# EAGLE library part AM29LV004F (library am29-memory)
4-Megabit FLASH MEMORY (512 K x 8 bit/256 K x 16 bit) 3 V-only
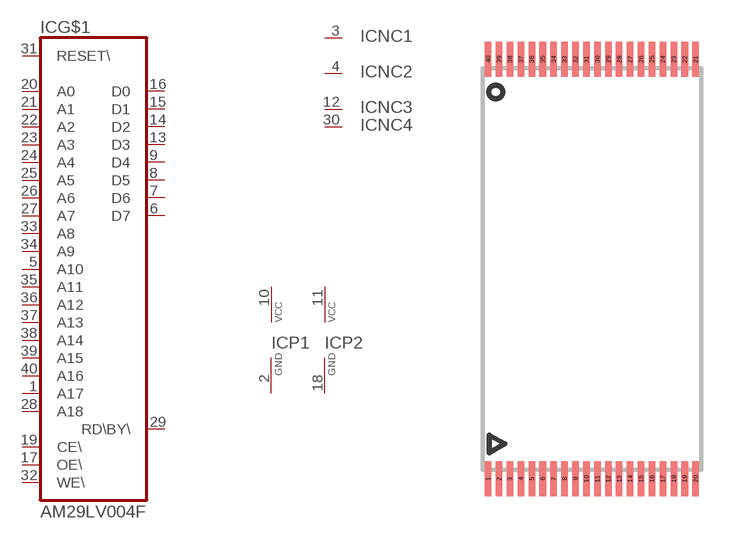
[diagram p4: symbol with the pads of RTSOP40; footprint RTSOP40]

Designator prefix IC; gates G$1=29LV004 NC1=NC NC2=NC NC3=NC NC4=NC P1=VCC-GND P2=VCC-GND

## AM29LV004F  [RTSOP40]
1  G$1:A17  in
2  P1:GND  pwr
3  NC1:NC  nc
4  NC2:NC  nc
5  G$1:A10  in
6  G$1:D7  hiz
7  G$1:D6  hiz
8  G$1:D5  hiz
9  G$1:D4  hiz
10  P1:VCC  pwr
11  P2:VCC  pwr
12  NC3:NC  nc
13  G$1:D3  hiz
14  G$1:D2  hiz
15  G$1:D1  hiz
16  G$1:D0  hiz
17  G$1:OE\  in
18  P2:GND  pwr
19  G$1:CE\  in
20  G$1:A0  in
21  G$1:A1  in
22  G$1:A2  in
23  G$1:A3  in
24  G$1:A4  in
25  G$1:A5  in
26  G$1:A6  in
27  G$1:A7  in
28  G$1:A18  in
29  G$1:RD\BY\  out
30  NC4:NC  nc
31  G$1:RESET\  in
32  G$1:WE\  in
33  G$1:A8  in
34  G$1:A9  in
35  G$1:A11  in
36  G$1:A12  in
37  G$1:A13  in
38  G$1:A14  in
39  G$1:A15  in
40  G$1:A16  in

## Footprint RTSOP40 (pad centres in mm)
Reverse TSOP40
smd 0.3 x 1.6: 1 -4.75,-9.6; 2 -4.25,-9.6; 3 -3.75,-9.6; 4 -3.25,-9.6; 5 -2.75,-9.6; 6 -2.25,-9.6; 7 -1.75,-9.6; 8 -1.25,-9.6; 9 -0.75,-9.6; 10 -0.25,-9.6; 11 0.25,-9.6; 12 0.75,-9.6; 13 1.25,-9.6; 14 1.75,-9.6; 15 2.25,-9.6; 16 2.75,-9.6; 17 3.25,-9.6; 18 3.75,-9.6; 19 4.25,-9.6; 20 4.75,-9.6; 21 4.75,9.6; 22 4.25,9.6; 23 3.75,9.6; 24 3.25,9.6; 25 2.75,9.6; 26 2.25,9.6; 27 1.75,9.6; 28 1.25,9.6; 29 0.75,9.6; 30 0.25,9.6; 31 -0.25,9.6; 32 -0.75,9.6; 33 -1.25,9.6; 34 -1.75,9.6; 35 -2.25,9.6; 36 -2.75,9.6; 37 -3.25,9.6; 38 -3.75,9.6; 39 -4.25,9.6; 40 -4.75,9.6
